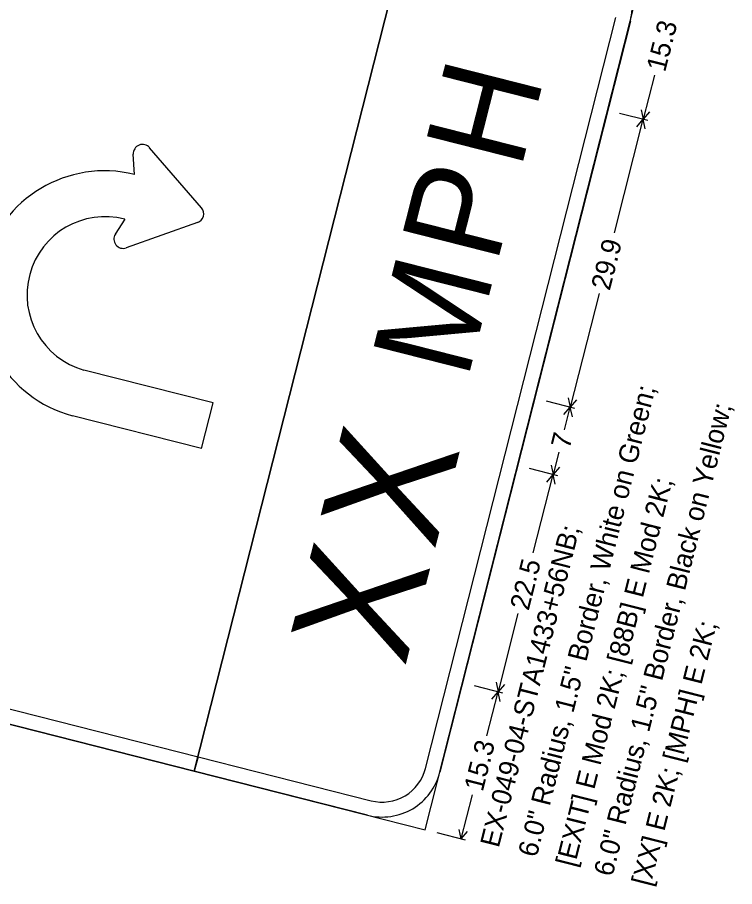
# Model space of a CAD drawing. Extents: x 670257 to 671518, y 737783 to 738188.
# Drawn here: x 670960.88 to 670969.91, y 737991.73 to 738002.67 of the extents above; entities that cross this region are included whole.
import ezdxf

# ---------------------------------------------------------------- set-up
doc = ezdxf.new("R2010")
doc.units = 0
doc.layers.add('R_SIGN', color=7, linetype='Continuous')

msp = doc.modelspace()

# ---------------------------------------------------------------- linework, layer by layer
at = {"layer": 'R_SIGN'}
for p, q in [((670963.11, 737993.18), (670965.876, 738004.085)), ((670965.876, 738004.085), (670963.11, 737993.18)), ((670966.018, 737992.443), (670968.784, 738003.347)), ((670966.021, 737993.216), (670968.418, 738002.666)), ((670968.6, 738002.62), (670966.203, 737993.17)), ((670968.903, 738001.94), (670968.762, 738001.384)), ((670968.736, 738001.504), (670968.762, 738001.384)), ((670968.822, 738001.369), (670968.464, 738001.459)), ((670968.822, 738001.369), (670968.464, 738001.459)), ((670968.842, 738001.477), (670968.762, 738001.384)), ((670968.4, 737999.955), (670968.762, 738001.384)), ((670968.682, 738001.291), (670968.762, 738001.384)), ((670968.788, 738001.264), (670968.762, 738001.384)), ((670963.201, 738000.271), (670962.548, 738001.027)), ((670962.357, 738000.69), (670962.342, 738000.944)), ((670962.235, 738000.127), (670962.116, 737999.94)), ((670963.151, 738000.084), (670962.254, 737999.766)), ((670968.206, 737999.19), (670967.843, 737997.761)), ((670963.348, 737997.816), (670961.721, 737998.228)), ((670963.203, 737997.241), (670963.348, 737997.816)), ((670967.903, 737997.746), (670967.545, 737997.837)), ((670967.817, 737997.881), (670967.843, 737997.761)), ((670967.924, 737997.854), (670967.843, 737997.761)), ((670967.763, 737997.668), (670967.843, 737997.761)), ((670967.771, 737997.477), (670967.843, 737997.761)), ((670967.87, 737997.641), (670967.843, 737997.761)), ((670963.203, 737997.241), (670961.576, 737997.654)), ((670967.7, 737997.197), (670967.628, 737996.913)), ((670967.602, 737997.033), (670967.628, 737996.913)), ((670967.688, 737996.898), (670967.33, 737996.988)), ((670967.378, 737995.929), (670967.628, 737996.913)), ((670967.548, 737996.82), (670967.628, 737996.913)), ((670967.709, 737997.006), (670967.628, 737996.913)), ((670967.654, 737996.793), (670967.628, 737996.913)), ((670952.206, 737995.946), (670963.11, 737993.18)), ((670952.979, 737995.943), (670963.157, 737993.362)), ((670963.11, 737993.18), (670952.933, 737995.761)), ((670967.185, 737995.164), (670966.935, 737994.179)), ((670966.909, 737994.3), (670966.935, 737994.179)), ((670966.994, 737994.164), (670966.637, 737994.255)), ((670966.794, 737993.624), (670966.935, 737994.179)), ((670966.855, 737994.086), (670966.935, 737994.179)), ((670967.015, 737994.272), (670966.935, 737994.179)), ((670966.961, 737994.059), (670966.935, 737994.179)), ((670963.157, 737993.362), (670963.11, 737993.18)), ((670963.11, 737993.18), (670963.157, 737993.362)), ((670963.157, 737993.362), (670965.338, 737992.809)), ((670963.157, 737993.362), (670963.157, 737993.362)), ((670966.021, 737993.216), (670966.021, 737993.216)), ((670963.11, 737993.18), (670963.11, 737993.18)), ((670963.11, 737993.18), (670966.018, 737992.443)), ((670965.291, 737992.627), (670963.11, 737993.18)), ((670966.607, 737992.885), (670966.466, 737992.329)), ((670966.018, 737992.443), (670966.018, 737992.443)), ((670966.439, 737992.449), (670966.466, 737992.329)), ((670966.525, 737992.314), (670966.167, 737992.405)), ((670966.546, 737992.422), (670966.466, 737992.329))]:
    msp.add_line(p, q, dxfattribs=at)
for centre, radius, start, end in [((670967.873, 738002.805), 0.75, 345.7686, 75.7688), ((670962.459, 738000.951), 0.117, 40.7767, 183.2283), ((670961.982, 737999.168), 1.568, 76.1684, 254.9793), ((670963.112, 738000.194), 0.117, 289.4736, 40.7767), ((670961.987, 737999.175), 0.983, 75.3868, 254.3334), ((670962.215, 737999.877), 0.117, 147.5362, 289.4736), ((670965.476, 737993.354), 0.562, 255.7684, 345.7686), ((670965.476, 737993.354), 0.75, 255.7684, 345.7686)]:
    msp.add_arc(centre, radius, start, end, dxfattribs=at)

# ---------------------------------------------------------------- texts
for s, height, p in [('15.3', 0.2461, (670969.037, 738001.969)), ('H', 1.25, (670967.218, 738000.731)), ('P', 1.25, (670966.917, 737999.543)), ('29.9', 0.2461, (670968.34, 737999.219)), ('M', 1.25, (670966.548, 737998.089)), ('6.0" Radius, 1.5" Border, White on Green; ', 0.24606, (670967.42, 737992.087)), ('6.0" Radius, 1.5" Border, Black on Yellow; ', 0.24606, (670968.374, 737991.845)), ('X', 1.5, (670966.133, 737995.946)), ('7', 0.246, (670967.834, 737997.226)), ('[EXIT] E Mod 2K; [88B] E Mod 2K; ', 0.24606, (670967.897, 737991.966)), ('EX-049-04-STA1433+56NB; ', 0.24606, (670966.943, 737992.208)), ('X', 1.5, (670965.761, 737994.477)), ('22.5', 0.2461, (670967.319, 737995.193)), ('[XX] E 2K; [MPH] E 2K; ', 0.24606, (670968.851, 737991.724)), ('15.3', 0.2461, (670966.741, 737992.914))]:
    msp.add_text(s, height=height, rotation=75.7686, dxfattribs=at).set_placement(p)

doc.saveas('drawing.dxf')
